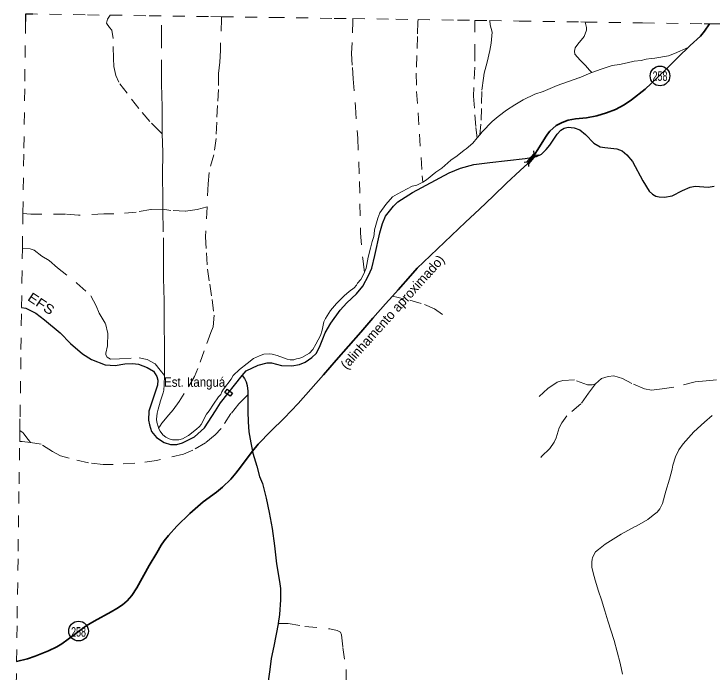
# Model space of a CAD drawing. Extents: x 703.1 to 728.9, y 7316.2 to 7344.3.
# Drawn here: x 703.36 to 709.23, y 7338.75 to 7344.29 of the extents above; entities that cross this region are included whole.
import ezdxf
from ezdxf.enums import TextEntityAlignment as Align

# ---------------------------------------------------------------- set-up
doc = ezdxf.new("R2010")
doc.units = 0
doc.header["$LTSCALE"] = 0.032
for name, pattern in [('DOTTED', [1.5, 0.3, -1.2]), ('LONG_DASHED', [7.5, 6, -1.5]), ('MEDIUM_DASHED', [4.5, 3, -1.5]), ('SHORT_DASHED', [2.7, 1.5, -1.2])]:
    doc.linetypes.add(name, pattern=pattern)
for name, color, linetype, lineweight in [('10', 7, 'Continuous', 25), ('13', 7, 'Continuous', 25), ('15', 7, 'Continuous', 25), ('2', 7, 'Continuous', 35), ('28', 7, 'Continuous', 25), ('4', 7, 'LONG_DASHED', 25), ('5', 7, 'LONG_DASHED', 13), ('58', 7, 'SHORT_DASHED', 13), ('6', 7, 'MEDIUM_DASHED', 13), ('63', 7, 'Continuous', 25), ('7', 7, 'DOTTED', 13)]:
    doc.layers.add(name, color=color, linetype=linetype, lineweight=lineweight)
doc.layers.add('61', color=7, linetype='Continuous')

msp = doc.modelspace()

# ---------------------------------------------------------------- linework, layer by layer
at = {"layer": '10'}
for p, q in [((707.6923, 7343.0329), (707.7529, 7343.1028)), ((707.7778, 7343.1046), (707.7529, 7343.1028)), ((707.6772, 7343.0461), (707.6523, 7343.0445)), ((707.6941, 7343.0082), (707.6923, 7343.0329))]:
    msp.add_line(p, q, dxfattribs=at)
msp.add_lwpolyline([(707.6772, 7343.0461), (707.7379, 7343.1159), (707.7361, 7343.1409)], dxfattribs=at)
at = {"layer": '13'}
for centre in [(708.7968, 7343.7715), (703.9028, 7339.0988)]:
    msp.add_circle(centre, 0.083, dxfattribs=at)
at = {"layer": '15'}
for points in [[(707.7272, 7343.0887), (707.7566, 7343.0941), (707.7983, 7343.1139), (707.839, 7343.1525), (707.8692, 7343.19), (707.9307, 7343.2808), (707.9609, 7343.3152), (707.9896, 7343.3334), (708.024, 7343.3407), (708.0741, 7343.3355), (708.121, 7343.3167), (708.171, 7343.2802), (708.2398, 7343.2062), (708.2935, 7343.1743), (708.3311, 7343.1681), (708.4322, 7343.1587), (708.4791, 7343.141), (708.5177, 7343.1065), (708.5656, 7343.0502), (708.6511, 7342.8896), (708.7048, 7342.8014), (708.733, 7342.7764), (708.7622, 7342.7586), (708.7903, 7342.7534), (708.8341, 7342.7524), (708.8988, 7342.7639), (708.9874, 7342.8066), (709.0494, 7342.8364), (709.0932, 7342.8426), (709.2026, 7342.8353), (709.2527, 7342.8447)], [(705.2805, 7341.249), (705.3144, 7341.2891), (705.4135, 7341.3381), (705.4896, 7341.3559), (705.5271, 7341.3559), (705.6116, 7341.335), (705.697, 7341.3308), (705.7622, 7341.3439), (705.8091, 7341.3637), (705.8654, 7341.4023), (705.9019, 7341.4346), (705.9321, 7341.4899), (705.9592, 7341.5598), (705.9785, 7341.6103), (706.0275, 7341.6896), (706.1047, 7341.8002), (706.1604, 7341.8612), (706.242, 7341.9388), (706.296, 7342.0009), (706.3444, 7342.0912), (706.3715, 7342.1548), (706.3966, 7342.2601), (706.4398, 7342.4515), (706.4602, 7342.5293), (706.4873, 7342.5908), (706.554, 7342.6763), (706.5915, 7342.7107), (706.7135, 7342.7911), (707.0231, 7342.9549), (707.1175, 7342.995), (707.2291, 7343.0253), (707.3656, 7343.0419), (707.6623, 7343.0769), (707.7272, 7343.0887)], [(703.4233, 7341.8238), (703.4588, 7341.8181), (703.5442, 7341.7754), (703.6153, 7341.7198), (703.7487, 7341.6082), (703.8342, 7341.5185), (703.9364, 7341.433), (704.0119, 7341.3856), (704.1277, 7341.3397), (704.21, 7341.3334), (704.2924, 7341.348), (704.3581, 7341.3522), (704.4086, 7341.3444), (704.4805, 7341.3184), (704.5327, 7341.2871), (704.5619, 7341.2422), (704.5692, 7341.2099), (704.5671, 7341.1682), (704.4936, 7340.9486), (704.4915, 7340.8746), (704.4988, 7340.836), (704.516, 7340.7791), (704.5597, 7340.729), (704.6223, 7340.6863), (704.6765, 7340.6696), (704.7307, 7340.6685), (704.7787, 7340.6821), (704.8777, 7340.7343), (704.9617, 7340.8099), (705.0555, 7340.9538), (705.0988, 7341.019), (705.2805, 7341.249)]]:
    msp.add_lwpolyline(points, dxfattribs=at)
at = {"layer": '2'}
for points in [[(709.2122, 7344.2106), (709.1714, 7344.1481), (709.1365, 7344.107), (709.0498, 7344.0269), (709.0338, 7344.0113)], [(709.0338, 7344.0113), (708.9605, 7343.9402), (708.8708, 7343.8514), (708.7733, 7343.7565), (708.6708, 7343.6616), (708.5556, 7343.5708), (708.4942, 7343.5285), (708.4219, 7343.4899), (708.3453, 7343.4599), (708.2656, 7343.4353), (708.1791, 7343.4205), (708.0855, 7343.4094), (708.0241, 7343.3987), (707.9744, 7343.3806), (707.9235, 7343.3535), (707.8699, 7343.3062), (707.8502, 7343.282), (707.8338, 7343.2561), (707.7835, 7343.1739), (707.7283, 7343.0901), (707.7272, 7343.0887)], [(707.7272, 7343.0887), (707.6833, 7343.0359), (707.6188, 7342.9746), (707.5056, 7342.8686), (707.3929, 7342.7597), (707.2773, 7342.6504), (707.16, 7342.5407), (707.0427, 7342.4289), (706.9254, 7342.3171), (706.8065, 7342.2045), (706.7521, 7342.1544), (706.6962, 7342.0903), (706.5929, 7341.9716), (706.5443, 7341.9173)], [(706.5443, 7341.9173), (706.4867, 7341.8529), (706.3805, 7341.7333), (706.2801, 7341.6162), (706.1752, 7341.4979), (706.0703, 7341.3783), (705.9654, 7341.2571), (705.858, 7341.1351), (705.7506, 7341.0131), (705.6325, 7340.8898), (705.5215, 7340.7813), (705.4137, 7340.6708), (705.3673, 7340.6125)], [(705.3673, 7340.6125), (705.3392, 7340.5771), (705.2651, 7340.4773), (705.2267, 7340.4268), (705.184, 7340.3775), (705.1148, 7340.3093), (705.0651, 7340.2678), (704.9528, 7340.1864), (704.8388, 7340.0886), (704.7314, 7339.9818), (704.6593, 7339.9025), (704.6244, 7339.8577), (704.5987, 7339.8228), (704.5605, 7339.7587), (704.4966, 7339.651), (704.3931, 7339.4636), (704.3522, 7339.3987), (704.3132, 7339.3535), (704.274, 7339.3206), (704.2263, 7339.2882), (704.1762, 7339.2602), (704.0354, 7339.1809), (703.9678, 7339.1427), (703.8141, 7339.0293), (703.7634, 7338.9911), (703.7198, 7338.9652), (703.6512, 7338.9315), (703.5389, 7338.8884), (703.4744, 7338.8649), (703.3809, 7338.8423)]]:
    msp.add_lwpolyline(points, dxfattribs=at)
at = {"layer": '28'}
msp.add_lwpolyline([(705.1797, 7341.0748), (705.1331, 7341.1075), (705.1525, 7341.1353), (705.1992, 7341.1025)], close=True, dxfattribs=at)
at = {"layer": '4'}
for points in [[(705.2805, 7341.249), (705.3003, 7341.2237), (705.314, 7341.1963), (705.3216, 7341.1668), (705.3277, 7341.1196), (705.3275, 7341.0886)], [(705.3275, 7341.0886), (705.327, 7341.0114), (705.3281, 7340.9464), (705.3315, 7340.8587), (705.3373, 7340.7752), (705.353, 7340.6821), (705.3673, 7340.6125)], [(705.3673, 7340.6125), (705.3705, 7340.5972), (705.404, 7340.4877), (705.4256, 7340.4008), (705.4509, 7340.3405), (705.4807, 7340.218), (705.5071, 7340.0975), (705.5313, 7339.9619), (705.5509, 7339.8174), (705.569, 7339.6634), (705.5946, 7339.5148), (705.6012, 7339.4559), (705.6012, 7339.3614), (705.5953, 7339.2375), (705.5829, 7339.1631)], [(705.5829, 7339.1631), (705.5823, 7339.1594), (705.5457, 7338.9725), (705.5242, 7338.8678), (705.5119, 7338.7753), (705.4907, 7338.6165), (705.4777, 7338.4761), (705.4684, 7338.3385), (705.4622, 7338.0886), (705.4455, 7337.9352), (705.4232, 7337.7866), (705.4003, 7337.7058), (705.3757, 7337.6278)]]:
    msp.add_lwpolyline(points, dxfattribs=at)
at = {"layer": '5'}
for points in [[(704.6001, 7344.1983), (704.6001, 7343.8912), (704.6017, 7343.7039), (704.6053, 7343.5101), (704.6063, 7343.3195), (704.6072, 7343.2839)], [(708.2218, 7343.8005), (708.3002, 7343.8284), (708.3948, 7343.8592), (708.457, 7343.8683), (708.5198, 7343.8814), (708.58, 7343.8965), (708.6386, 7343.9011), (708.6792, 7343.9129), (708.7224, 7343.9181), (708.7531, 7343.9201), (708.8683, 7343.9417), (708.9197, 7343.9607), (709.0338, 7344.0113)], [(707.4345, 7343.4302), (707.5058, 7343.4845), (707.5752, 7343.5284), (707.6453, 7343.571), (707.7419, 7343.6181), (707.8139, 7343.6404), (707.9323, 7343.6915), (708.1172, 7343.7557), (708.2138, 7343.7976), (708.2218, 7343.8005)], [(707.2793, 7343.2773), (707.2993, 7343.3025), (707.3844, 7343.3876), (707.4345, 7343.4302)], [(704.6072, 7343.2839), (704.6112, 7343.1289), (704.6089, 7342.9338), (704.6125, 7342.7387), (704.6136, 7342.6516)], [(707.0895, 7343.0982), (707.1478, 7343.1473), (707.1661, 7343.1572), (707.2224, 7343.2056), (707.2576, 7343.2499), (707.2793, 7343.2773)], [(706.7994, 7342.8777), (706.8303, 7342.8965), (706.9098, 7342.9626), (706.9609, 7342.9954), (707.0375, 7343.0622), (707.0895, 7343.0982)], [(706.3097, 7342.1208), (706.3223, 7342.1547), (706.3407, 7342.2463), (706.3587, 7342.3229), (706.3738, 7342.3786), (706.3895, 7342.4198), (706.3914, 7342.4388), (706.3943, 7342.4774), (706.4218, 7342.5757), (706.4392, 7342.6195), (706.4889, 7342.6909), (706.5459, 7342.7551), (706.5832, 7342.7767), (706.7105, 7342.8435), (706.7491, 7342.852), (706.7851, 7342.869), (706.7994, 7342.8777)], [(704.6136, 7342.6516), (704.6165, 7342.4087), (704.6168, 7342.2607), (704.6184, 7342.0695), (704.6227, 7341.877), (704.6237, 7341.6858), (704.626, 7341.4939), (704.6257, 7341.302), (704.6251, 7341.2506)], [(704.577, 7340.8071), (704.5893, 7340.7802), (704.6122, 7340.752), (704.6361, 7340.7324), (704.6649, 7340.716), (704.693, 7340.7081), (704.7467, 7340.7075), (704.7781, 7340.7179), (704.8279, 7340.7455), (704.896, 7340.7978), (704.9199, 7340.822), (704.9349, 7340.8377), (704.9808, 7340.9235), (705.0024, 7340.9523), (705.0381, 7341.0099), (705.0819, 7341.0715), (705.0996, 7341.0905), (705.1094, 7341.1127), (705.1238, 7341.1357), (705.1863, 7341.2202), (705.204, 7341.2503), (705.2564, 7341.3014), (705.3222, 7341.3505), (705.3752, 7341.3924), (705.425, 7341.4167), (705.4636, 7341.4291), (705.5133, 7341.4337), (705.533, 7341.4304), (705.5752, 7341.418), (705.659, 7341.3872), (705.6845, 7341.3833), (705.714, 7341.3833), (705.7382, 7341.3898), (705.7579, 7341.3937), (705.7827, 7341.4009), (705.8472, 7341.4395), (705.8734, 7341.469), (705.9002, 7341.5135), (705.9401, 7341.5882), (705.9535, 7341.6327), (705.9673, 7341.7021), (705.9804, 7341.731), (706.0226, 7341.7984), (706.0737, 7341.8567), (706.1391, 7341.9196), (706.1807, 7341.9582), (706.2226, 7341.989), (706.2422, 7342.0093), (706.2507, 7342.0263), (706.2775, 7342.0584), (706.304, 7342.1055), (706.3097, 7342.1208)], [(704.6251, 7341.2506), (704.6241, 7341.171), (704.6214, 7341.1272), (704.6158, 7341.103), (704.5936, 7341.0375), (704.5831, 7341.0047), (704.5733, 7340.9674), (704.5654, 7340.9334), (704.5579, 7340.883), (704.5611, 7340.8568), (704.5749, 7340.8116), (704.577, 7340.8071)], [(709.2361, 7340.9125), (709.1718, 7340.8571), (709.0813, 7340.7751), (708.9922, 7340.6742), (708.9551, 7340.6242), (708.9267, 7340.5665), (708.9053, 7340.4961), (708.8988, 7340.4623), (708.8778, 7340.378), (708.8445, 7340.276), (708.8189, 7340.1728), (708.7944, 7340.1267), (708.7729, 7340.1001), (708.7406, 7340.0732), (708.6946, 7340.0393), (708.6019, 7339.9843), (708.5813, 7339.9769), (708.4701, 7339.9138), (708.3365, 7339.8311), (708.2778, 7339.7865), (708.2551, 7339.7646), (708.2359, 7339.7361), (708.2286, 7339.7161), (708.2268, 7339.7037), (708.2218, 7339.6783), (708.2241, 7339.6349), (708.2436, 7339.5587), (708.2524, 7339.5263), (708.2796, 7339.4336), (708.3051, 7339.3609), (708.3319, 7339.269), (708.3586, 7339.1851), (708.4101, 7339.0204), (708.4356, 7338.9238), (708.4628, 7338.8291), (708.4814, 7338.7352)]]:
    msp.add_lwpolyline(points, dxfattribs=at)
at = {"layer": '58'}
for points in [[(703.4345, 7342.6136), (703.4424, 7343.1632), (703.4504, 7343.7284), (703.4584, 7344.2935)], [(703.4584, 7344.2935), (703.9776, 7344.2861), (704.1689, 7344.2834)], [(704.1689, 7344.2834), (704.4968, 7344.2787), (705.0159, 7344.2713), (705.1057, 7344.27)], [(705.1057, 7344.27), (705.5351, 7344.2638), (706.0543, 7344.2564), (706.2121, 7344.2541)], [(706.2121, 7344.2541), (706.5735, 7344.2489), (706.76, 7344.2462)], [(706.76, 7344.2462), (707.0926, 7344.2414), (707.2393, 7344.2393), (707.3641, 7344.2375)], [(707.3641, 7344.2375), (707.6118, 7344.2339), (708.131, 7344.2263), (708.1672, 7344.2258)], [(708.1672, 7344.2258), (708.6502, 7344.2188), (709.1693, 7344.2112), (709.2122, 7344.2106), (709.4762, 7344.2067)], [(703.4304, 7342.3232), (703.4343, 7342.5981), (703.4345, 7342.6136)], [(703.4233, 7341.8238), (703.4263, 7342.033), (703.4304, 7342.3232)], [(703.4086, 7340.7864), (703.4102, 7340.9028), (703.4183, 7341.4679), (703.4233, 7341.8238)], [(703.3809, 7338.8423), (703.3861, 7339.2075), (703.3942, 7339.7726), (703.4022, 7340.3377), (703.4073, 7340.6952), (703.4086, 7340.7864)], [(703.3592, 7337.3202), (703.362, 7337.5121), (703.37, 7338.0772), (703.3781, 7338.6424), (703.3809, 7338.8423)]]:
    msp.add_lwpolyline(points, dxfattribs=at)
at = {"layer": '6'}
for points in [[(705.1057, 7344.27), (705.1051, 7344.25), (705.0967, 7343.9862), (705.093, 7343.8872), (705.0804, 7343.7911), (705.0804, 7343.6585), (705.0718, 7343.5237), (705.0654, 7343.3829), (705.0614, 7343.2444), (705.0401, 7343.1081), (705.0011, 7342.9599), (704.9943, 7342.8631), (704.9847, 7342.6687)], [(707.3641, 7344.2375), (707.3671, 7344.2029), (707.3838, 7344.1394), (707.3749, 7344.0481), (707.3632, 7343.9852), (707.3418, 7343.8866), (707.317, 7343.7942), (707.31, 7343.7519), (707.2967, 7343.64), (707.2953, 7343.4986), (707.2892, 7343.3656), (707.2793, 7343.2773)], [(704.6136, 7342.6516), (704.5123, 7342.6478), (704.3887, 7342.6255), (704.2008, 7342.6113), (704.1152, 7342.6121), (703.9011, 7342.5987), (703.7924, 7342.6076), (703.5025, 7342.6091), (703.4345, 7342.6136)], [(704.9847, 7342.6687), (704.9705, 7342.418), (704.9802, 7342.2824), (704.988, 7342.1462), (705.0077, 7342.0188), (705.0275, 7341.8901), (705.0429, 7341.7583), (705.0351, 7341.6604), (705.0154, 7341.6133), (704.9611, 7341.4576), (704.908, 7341.3101), (704.8801, 7341.2404), (704.7914, 7341.0992), (704.7502, 7341.0301), (704.7, 7340.9598), (704.6615, 7340.9184), (704.6034, 7340.8487), (704.5897, 7340.8271), (704.577, 7340.8071)], [(704.9847, 7342.6687), (704.9013, 7342.6478), (704.8001, 7342.6329), (704.6802, 7342.6389), (704.6136, 7342.6516)], [(703.4304, 7342.3232), (703.4957, 7342.3165), (703.529, 7342.3045), (703.5939, 7342.2559), (703.6556, 7342.2194), (703.7249, 7342.1555), (703.8888, 7342.0278), (704.0058, 7341.9214), (704.0508, 7341.8373), (704.0758, 7341.7757), (704.129, 7341.6878), (704.1484, 7341.6032), (704.1465, 7341.5011), (704.1326, 7341.4383), (704.1326, 7341.4247), (704.1425, 7341.4039), (704.1708, 7341.3881), (704.2467, 7341.3898), (704.4133, 7341.3996), (704.4802, 7341.3843), (704.5473, 7341.3483), (704.5898, 7341.2948), (704.6251, 7341.2506)], [(708.2534, 7341.1799), (708.227, 7341.1709), (708.1867, 7341.1709), (708.0765, 7341.213), (707.9798, 7341.2094), (707.9306, 7341.1951), (707.8527, 7341.1404), (707.7717, 7341.0652)], [(709.6726, 7341.2493), (709.4726, 7341.2292), (709.1861, 7341.205), (709.0925, 7341.1978), (708.9143, 7341.1512), (708.8149, 7341.1387), (708.724, 7341.1261), (708.6658, 7341.1369), (708.5601, 7341.1825), (708.4809, 7341.2247), (708.4074, 7341.2479), (708.36, 7341.2417), (708.3053, 7341.2238), (708.2534, 7341.1799)], [(708.2534, 7341.1799), (708.1952, 7341.1001), (708.1316, 7341.0106), (708.0121, 7340.9111), (707.9709, 7340.8529), (707.9485, 7340.8108), (707.9239, 7340.7256), (707.9069, 7340.6898), (707.8684, 7340.6361), (707.7994, 7340.5671), (707.7945, 7340.5608)], [(705.3275, 7341.0886), (705.2968, 7341.0554), (705.2528, 7341.0113), (705.1856, 7340.9298), (705.1041, 7340.8034), (705.0514, 7340.75), (704.9717, 7340.6822), (704.8656, 7340.6223), (704.7859, 7340.5891), (704.5586, 7340.5342), (704.3779, 7340.5119), (704.195, 7340.5017), (704.1109, 7340.5003), (703.9854, 7340.5155), (703.8238, 7340.5537), (703.7509, 7340.5725), (703.6831, 7340.6093), (703.5871, 7340.6714), (703.4991, 7340.6865)], [(703.4991, 7340.6865), (703.4273, 7340.6933), (703.4073, 7340.6952)]]:
    msp.add_lwpolyline(points, dxfattribs=at)
at = {"layer": '63'}
msp.add_lwpolyline([(703.5174, 7344.2906), (703.4558, 7344.2906), (703.4558, 7344.2299)], dxfattribs=at)
at = {"layer": '7'}
for points in [[(704.6072, 7343.2839), (704.5872, 7343.3038), (704.5029, 7343.3876), (704.4094, 7343.4964), (704.3111, 7343.6268), (704.2416, 7343.7183), (704.2155, 7343.7765), (704.1995, 7343.8524), (704.1965, 7343.9186), (704.194, 7344.0881), (704.1817, 7344.1568), (704.1632, 7344.1787), (704.137, 7344.2167), (704.1472, 7344.2496), (704.1689, 7344.2834)], [(706.2121, 7344.2541), (706.2114, 7344.2341), (706.2051, 7344.0532), (706.2002, 7343.9611), (706.2081, 7343.8425), (706.2149, 7343.7474), (706.233, 7343.5108), (706.2531, 7343.2476), (706.2688, 7342.884), (706.2717, 7342.6939), (706.2771, 7342.4494), (706.2952, 7342.2353), (706.3072, 7342.1409), (706.3097, 7342.1208)], [(706.76, 7344.2462), (706.7593, 7344.2262), (706.755, 7344.1028), (706.751, 7343.9443), (706.7456, 7343.7954), (706.7486, 7343.6409), (706.7609, 7343.4602), (706.7713, 7343.2815), (706.7867, 7343.0849), (706.7951, 7342.9309), (706.7994, 7342.8777)], [(707.2393, 7344.2393), (707.2374, 7343.995), (707.2384, 7343.8443), (707.2304, 7343.6735), (707.2281, 7343.6005), (707.2393, 7343.4451), (707.2462, 7343.3377), (707.2576, 7343.2499)], [(708.1672, 7344.2258), (708.1787, 7344.1795), (708.1778, 7344.1565), (708.1583, 7344.1043), (708.1061, 7344.0388), (708.0831, 7344.0096), (708.076, 7343.9813), (708.0796, 7343.9556), (708.1247, 7343.9043), (708.1698, 7343.8591), (708.2041, 7343.8205), (708.2218, 7343.8005)], [(706.5443, 7341.9173), (706.6908, 7341.8838), (706.8157, 7341.8483), (706.8992, 7341.8127), (706.9657, 7341.7635)], [(703.4991, 7340.6865), (703.4581, 7340.738), (703.4374, 7340.7669), (703.4286, 7340.7729), (703.4086, 7340.7864)], [(705.5829, 7339.1631), (705.6669, 7339.1634), (705.8075, 7339.1376), (706.0183, 7339.117), (706.0806, 7339.1031), (706.1071, 7339.0905), (706.1164, 7339.0659), (706.1284, 7338.9611), (706.1546, 7338.775), (706.1563, 7338.6486), (706.1619, 7338.5282), (706.1881, 7338.4264), (706.2232, 7338.3368), (706.2372, 7338.2731), (706.2498, 7338.0794), (706.2641, 7337.9955), (706.277, 7337.8977)]]:
    msp.add_lwpolyline(points, dxfattribs=at)

# ---------------------------------------------------------------- texts
at = {"layer": '61', "width": 0.7}
for p in [(708.7967, 7343.7306), (703.9028, 7339.0518)]:
    msp.add_text('258', height=0.08, dxfattribs=at).set_placement(p, align=Align.CENTER)
at = {"layer": '61'}
msp.add_text('(alinhamento aproximado)', height=0.08, rotation=48.09, dxfattribs=at).set_placement((706.5748, 7341.7579), align=Align.CENTER)
at = {"layer": '61', "width": 1.15}
msp.add_text('EFS', height=0.08, rotation=326.398, dxfattribs=at).set_placement((703.5663, 7341.8216), align=Align.CENTER)
at = {"layer": '61', "width": 0.9}
msp.add_text('Est. Itanguá', height=0.08, dxfattribs=at).set_placement((704.6231, 7341.1551))

doc.saveas('drawing.dxf')
